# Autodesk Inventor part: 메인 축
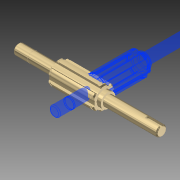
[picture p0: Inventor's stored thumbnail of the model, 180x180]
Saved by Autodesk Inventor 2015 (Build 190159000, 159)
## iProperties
Created: 2015-11
Part Number: 메인 축
Document SubType Name: 모델링
Designer: mdu
Mass: 168.566 g
Surface Area: 72.5104 cm^2
Volume: 21.4461 cm^3
Density: 7.86 g/cm^3
Material: 강철, 연강
Appearance: 강철
변환 표준: STEP AP214IS
파일 이름: C:\Users\SeoGD\Desktop\?쒗뿕\硫붿씤 異?.stp
전처리기: Build: 253, Release: 2010 SP1 - Date: Wed 07/29/2009
전송 단위: 밀리미터
불확실성: 0.01
Author: mdu
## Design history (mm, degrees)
sketch "스케치1"
  geometry: L1 (-69.5, 0)-(69.5, 0); L2 (69.5, 0)-(69.5, 5); L3 (69.5, 5)-(55.5, 5); L4 (55.5, 5)-(55.5, 4.8); L5 (55.5, 4.8)-(54.35, 4.8); L6 (54.35, 4.8)-(54.35, 5); L7 (54.35, 5)-(30.5, 5); L8 (30.5, 5)-(30.5, 9); L9 (30.5, 9)-(-13.5, 9); L10 (-13.5, 9)-(-13.5, 7); L11 (-13.5, 7)-(-17.5, 7); L12 (-17.5, 7)-(-17.5, 5); L13 (-17.5, 5)-(-69.5, 5); L14 (-69.5, 5)-(-69.5, 0); 2 further points
  constraints: 28 end point, 9 parallel, 4 collinear, 2 perpendicular, 1 coincident, 1 horizontal, 1 midpoint
  dimensions: "d2" = 1.15 distance between parallel lines of L6 L4; "d3" = 10 diameter of L3 L1; "d4" = 9.6 diameter of L5 L1; "d6" = 44 distance between parallel lines of L10 L8; "d7" = 4 distance between parallel lines of L12 L10; "d8" = 14 diameter of L11 L1; "d9" = 18 diameter of L9 L1; "d33" = 52 distance from line of L12.end L14; "d37" = 39 distance between parallel lines of L8 L2; "d38" = 14 distance between parallel lines of L2 L4
revolve "회전1" sketch "스케치1" stored, may be unused: angle "d10" = 90 deg
sketch "스케치2"
  geometry: L1 (2.5, 10.712)-(2.5, 8.646); L2 (-2.5, 10.712)-(-2.5, 8.646); A1 r 9 centre (0, 0) between (2.5, 8.646) and (-2.5, 8.646) reference; A2 r 11 centre (0, 0) between (2.5, 10.712) and (-2.5, 10.712); 1 further point
  constraints: 4 end point, 4 point on circle, 2 parallel, 1 centre point, 1 coincident, 1 vertical
  dimensions: "d11" = 22 diameter of A2; "d12" = 5 distance between parallel lines of L1 L2
extrude "돌출1" join sketch "스케치2" stored distance "d13" = 10; taper "d14" = 0 deg
chamfer "모따기1" distance "d15" = 1; stored, may be unused: second distance "d16" = 2, angle "d17" = 45 deg
node "작업 평면1"
node "작업 평면2"
sketch "스케치3"
  geometry: L1 (2.5, 10.712)-(2.5, 10.198); L2 (-2.5, 10.712)-(-2.5, 10.198); A1 r 11 centre (0, 0) between (2.5, 10.712) and (-2.5, 10.712) reference; A2 r 10.5 centre (0, 0) between (2.5, 10.198) and (-2.5, 10.198); 1 further point
  constraints: 4 end point, 2 point on circle, 1 centre point, 1 coincident, 1 parallel, 1 vertical
  dimensions: "d19" = 21 diameter of A2
extrude "돌출2" cut sketch "스케치3" distance "d20" = 1.35; taper "d21" = 0 deg
node "작업 평면3"
sketch "스케치4"
  geometry: L1 (-26, -5)-(-26, 5) reference; L2 (-26, 1.5)-(-12.5, 1.5); L3 (-12.5, -1.5)-(-26, -1.5); A1 r 1.5 centre (-12.5, 0) between (-12.5, -1.5) and (-12.5, 1.5); 2 further points
  constraints: 4 end point, 2 perpendicular, 2 point on circle, 2 point on line, 2 tangent, 1 centre point, 1 horizontal alignment, 1 midpoint
  dimensions: "d25" = 3 distance between parallel lines of L3 L2; "d26" = 15 dimension on A1 L1
extrude "돌출3" cut sketch "스케치4" distance "d27" = 1.8; taper "d28" = 0 deg
chamfer "모따기2" distance "d29" = 1; stored, may be unused: second distance "d30" = 2, angle "d31" = 45 deg
node "솔리드1"
node "솔리드 본체"
node "곡면 본체"
mirror "대칭1"
pattern_circular "원형 패턴1" dims "d23" = 360 deg
node "솔리드2"
other parameters: "d18" = -1.65
